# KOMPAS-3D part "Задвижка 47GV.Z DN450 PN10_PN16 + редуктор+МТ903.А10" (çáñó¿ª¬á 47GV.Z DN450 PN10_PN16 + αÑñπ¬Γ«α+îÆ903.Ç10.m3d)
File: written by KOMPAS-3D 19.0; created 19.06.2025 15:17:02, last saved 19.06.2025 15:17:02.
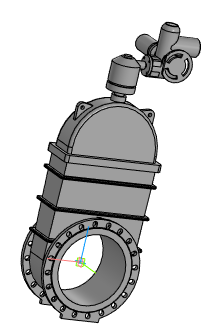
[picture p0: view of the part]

Document properties: Полное имя файла: Задвижка 47GV.Z DN450 PN10_PN16 + редуктор+МТ903.А10.a3d

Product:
- Part/product: Задвижка 47GV.Z DN450 PN10_PN16 + редуктор+МТ903.А10
    Масса: 1048.21

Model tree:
1. Операция без истории:1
